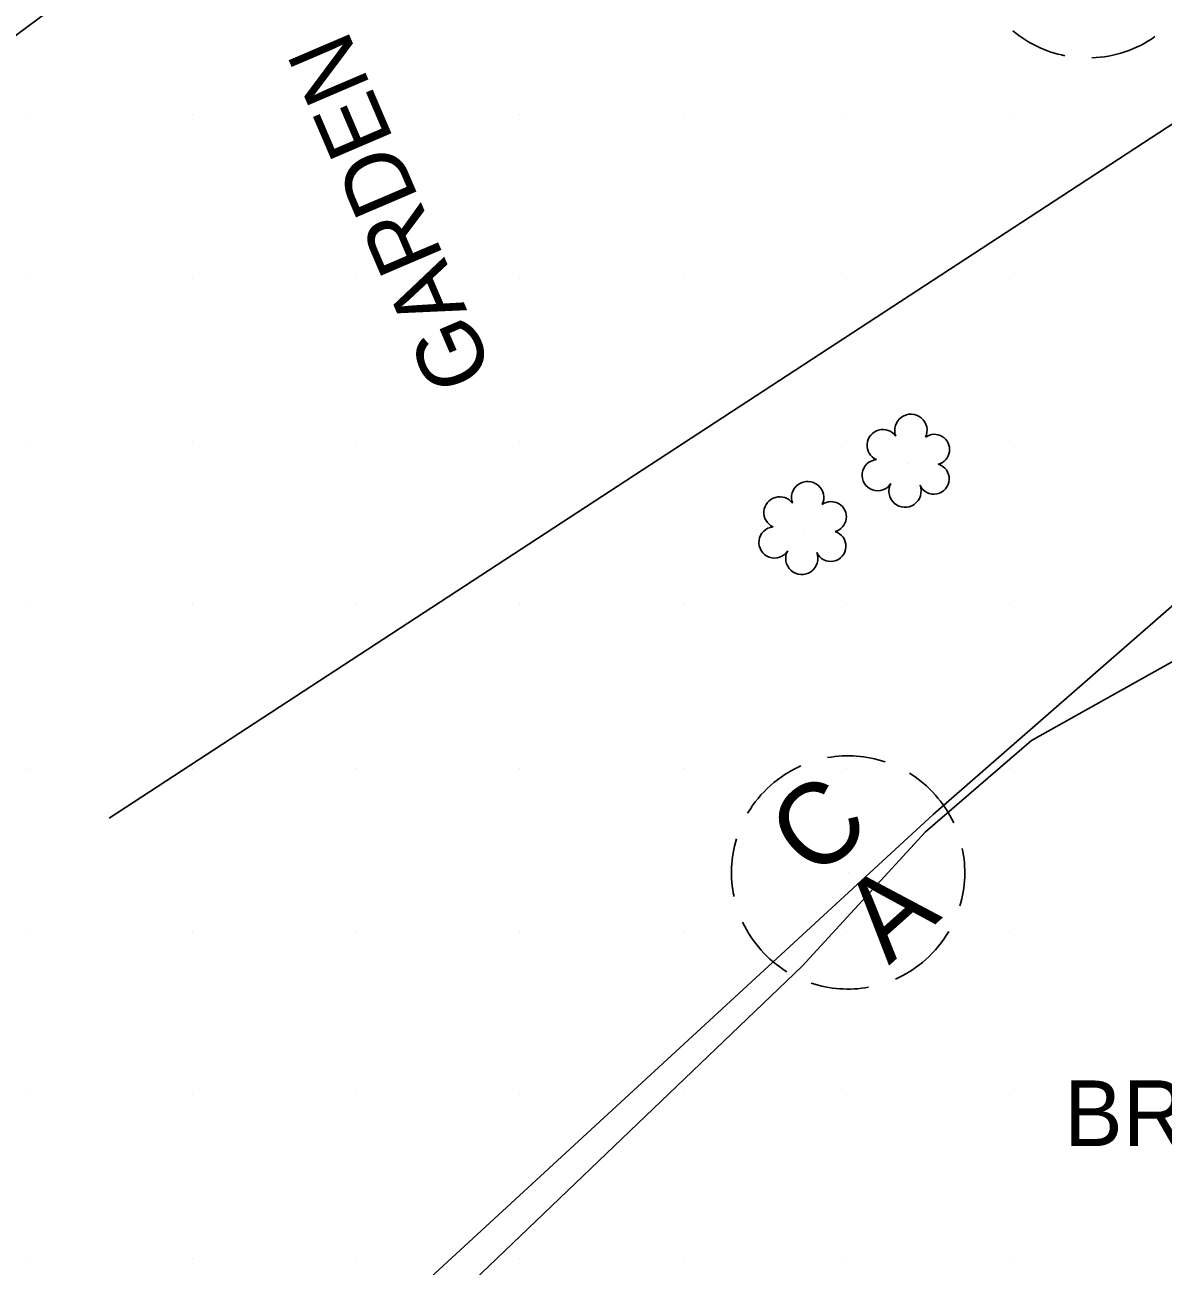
# Model space of a CAD drawing. Extents: x 1548934 to 1561348, y 809680 to 824075.
# Drawn here: x 1551639.7 to 1551709.4, y 810839.5 to 810915.5 of the extents above; entities that cross this region are included whole.
import ezdxf

# ---------------------------------------------------------------- set-up
doc = ezdxf.new("R2010")
doc.units = 0
for name, color, linetype in [('E_NCDOT_Vertical_Profile_Ground_Line', 7, 'Continuous'), ('Exist DTM QL2 LIDAR Elevation Point', 7, 'Continuous'), ('Exist Other Culture Area Outline', 7, 'Continuous'), ('Exist Other Culture Area Outline Text', 7, 'Continuous'), ('Exist Right of Way Control of Access CA Symbol CELL', 7, 'Continuous'), ('Exist Structure Major Bridge Seat Top Elevation', 7, 'Continuous'), ('Exist Vegetation Shrub CELL', 7, 'Continuous'), ('Exist Vegetation Woods Line', 7, 'Continuous'), ('P_NCDOT_Vertical_Profile_Grade_Minor_Road', 7, 'Continuous'), ('P_RDY_Dimension_Text', 7, 'Continuous')]:
    doc.layers.add(name, color=color, linetype=linetype)

msp = doc.modelspace()

# ---------------------------------------------------------------- linework, layer by layer
at = {"layer": 'E_NCDOT_Vertical_Profile_Ground_Line'}
for points in [[(1551669.226, 811276.996), (1551672.738, 811263.647), (1551679.608, 811234.972), (1551690.372, 811191.216), (1551702.412, 811145.663), (1551714.334, 811100.035), (1551727.001, 811053.454), (1551740.473, 811006.496), (1551755.133, 810959.341), (1551769.097, 810915.847), (1551778.934, 810888.327), (1551783.173, 810876.085)], [(1551650.087, 811272.175), (1551653.545, 811258.382), (1551661.249, 811229.547), (1551671.78, 811185.408), (1551683.851, 811140.035), (1551696.074, 811094.565), (1551708.619, 811047.914), (1551722.358, 811000.566), (1551736.976, 810952.927), (1551751.546, 810908.962), (1551760.885, 810880.923), (1551765.285, 810868.443)]]:
    msp.add_open_spline(points, degree=3, dxfattribs=at)
at = {"layer": 'Exist DTM QL2 LIDAR Elevation Point'}
for p, q in [((1551639.99, 810910.004), (1551639.99, 810910.004)), ((1551649.991, 810910.004), (1551649.991, 810910.004)), ((1551659.992, 810910.004), (1551659.992, 810910.004)), ((1551669.992, 810910.004), (1551669.992, 810910.004)), ((1551679.993, 810910.004), (1551679.993, 810910.004)), ((1551689.994, 810910.004), (1551689.994, 810910.004)), ((1551699.995, 810910.004), (1551699.995, 810910.004)), ((1551639.99, 810900.003), (1551639.99, 810900.003)), ((1551649.991, 810900.003), (1551649.991, 810900.003)), ((1551659.992, 810900.003), (1551659.992, 810900.003)), ((1551669.992, 810900.003), (1551669.992, 810900.003)), ((1551679.993, 810900.003), (1551679.993, 810900.003)), ((1551689.994, 810900.003), (1551689.994, 810900.003)), ((1551699.995, 810900.003), (1551699.995, 810900.003)), ((1551639.99, 810890.002), (1551639.99, 810890.002)), ((1551649.991, 810890.002), (1551649.991, 810890.002)), ((1551659.992, 810890.002), (1551659.992, 810890.002)), ((1551669.992, 810890.002), (1551669.992, 810890.002)), ((1551679.993, 810890.002), (1551679.993, 810890.002)), ((1551689.994, 810890.002), (1551689.994, 810890.002)), ((1551699.995, 810890.002), (1551699.995, 810890.002)), ((1551639.99, 810880.001), (1551639.99, 810880.001)), ((1551649.991, 810880.001), (1551649.991, 810880.001)), ((1551659.992, 810880.001), (1551659.992, 810880.001)), ((1551669.992, 810880.001), (1551669.992, 810880.001)), ((1551679.993, 810880.001), (1551679.993, 810880.001)), ((1551689.994, 810880.001), (1551689.994, 810880.001)), ((1551699.995, 810880.001), (1551699.995, 810880.001)), ((1551639.99, 810870), (1551639.99, 810870)), ((1551649.991, 810870), (1551649.991, 810870)), ((1551659.992, 810870), (1551659.992, 810870)), ((1551669.992, 810870), (1551669.992, 810870)), ((1551679.993, 810870), (1551679.993, 810870)), ((1551689.994, 810870), (1551689.994, 810870)), ((1551699.995, 810870), (1551699.995, 810870)), ((1551639.99, 810860), (1551639.99, 810860)), ((1551649.991, 810860), (1551649.991, 810860)), ((1551659.992, 810860), (1551659.992, 810860)), ((1551669.992, 810860), (1551669.992, 810860)), ((1551679.993, 810860), (1551679.993, 810860)), ((1551689.994, 810860), (1551689.994, 810860)), ((1551699.995, 810860), (1551699.995, 810860)), ((1551639.99, 810849.999), (1551639.99, 810849.999)), ((1551649.991, 810849.999), (1551649.991, 810849.999)), ((1551659.992, 810849.999), (1551659.992, 810849.999)), ((1551669.992, 810849.999), (1551669.992, 810849.999)), ((1551679.993, 810849.999), (1551679.993, 810849.999)), ((1551689.994, 810849.999), (1551689.994, 810849.999)), ((1551699.995, 810849.999), (1551699.995, 810849.999)), ((1551639.99, 810839.998), (1551639.99, 810839.998)), ((1551649.991, 810839.998), (1551649.991, 810839.998)), ((1551659.992, 810839.998), (1551659.992, 810839.998)), ((1551669.992, 810839.998), (1551669.992, 810839.998)), ((1551679.993, 810839.998), (1551679.993, 810839.998)), ((1551689.994, 810839.998), (1551689.994, 810839.998)), ((1551699.995, 810839.998), (1551699.995, 810839.998))]:
    msp.add_line(p, q, dxfattribs=at)
at = {"layer": 'Exist Other Culture Area Outline'}
for p, q in [((1551630.998, 810908.815), (1551700.718, 810960.615)), ((1551716.925, 810913.996), (1551644.86, 810866.935))]:
    msp.add_line(p, q, dxfattribs=at)
at = {"layer": 'Exist Right of Way Control of Access CA Symbol CELL'}
msp.add_line((1551690.094, 810863.607), (1551690.094, 810863.607), dxfattribs=at)
for centre, start, end in [((1551704.752, 810920.617), 230.21678, 258.8046), ((1551704.752, 810920.617), 272.03783, 305.19661), ((1551690.094, 810863.607), 71.53495, 100.12277), ((1551690.094, 810863.607), 113.91621, 149.52844), ((1551690.094, 810863.607), 25.14294, 58.30172), ((1551690.094, 810863.607), 163.32189, 191.9097), ((1551690.094, 810863.607), 343.32189, 11.9097), ((1551690.094, 810863.607), 205.14294, 238.30172), ((1551690.094, 810863.607), 293.91621, 329.52844), ((1551690.094, 810863.607), 251.53495, 280.12277)]:
    msp.add_arc(centre, 7.14, start, end, dxfattribs=at)
at = {"layer": 'Exist Vegetation Shrub CELL'}
for p, q in [((1551693.705, 810888.635), (1551693.705, 810888.635)), ((1551687.385, 810884.515), (1551687.385, 810884.515))]:
    msp.add_line(p, q, dxfattribs=at)
for centre, radius, start, end in [((1551693.933, 810890.675), 0.99, 334.83907, 200.47174), ((1551692.222, 810889.762), 0.968, 35.89076, 245.42165), ((1551695.377, 810889.504), 0.929, 284.45672, 126.08612), ((1551691.904, 810887.931), 0.955, 95.10992, 327.95341), ((1551695.342, 810887.706), 0.937, 204.99133, 73.46012), ((1551687.614, 810886.555), 0.99, 334.83907, 200.47174), ((1551693.576, 810886.951), 0.984, 151.27966, 21.38702), ((1551685.902, 810885.642), 0.968, 35.89076, 245.42165), ((1551689.057, 810885.384), 0.929, 284.45672, 126.08612), ((1551685.585, 810883.811), 0.955, 95.10992, 327.95341), ((1551689.022, 810883.586), 0.937, 204.99133, 73.46012), ((1551687.257, 810882.831), 0.984, 151.27966, 21.38702)]:
    msp.add_arc(centre, radius, start, end, dxfattribs=at)
at = {"layer": 'Exist Vegetation Woods Line'}
msp.add_lwpolyline([(1551659.009, 810830.794), (1551687.273, 810857.868), (1551694.83, 810866.102), (1551701.312, 810871.679), (1551710.401, 810876.775), (1551717.053, 810878.29), (1551720.9, 810876.861), (1551733.666, 810867.652), (1551749.063, 810849.427), (1551750.485, 810843.047), (1551748.423, 810838.374)], dxfattribs=at)
at = {"layer": 'P_NCDOT_Vertical_Profile_Grade_Minor_Road'}
msp.add_open_spline([(1551774.266, 810871.875), (1551769.963, 810884.281), (1551760.748, 810912.225), (1551745.661, 810955.91), (1551731.498, 811003.541), (1551717.995, 811050.78), (1551705.433, 811097.256), (1551693.244, 811142.664), (1551681.433, 811187.985), (1551670.2, 811231.948), (1551663.062, 811260.975), (1551659.556, 811274.891)], degree=3, dxfattribs=at)
at = {"layer": 'P_RDY_Dimension_Text'}
msp.add_lwpolyline([(1551760.849, 810852.377), (1551753.881, 810847.549), (1551716.432, 810885.612), (1551695.287, 810867.156), (1551642.57, 810818.585), (1551625.512, 810802.672), (1551609.652, 810768.783), (1551603.272, 810753.552)], dxfattribs=at)

# ---------------------------------------------------------------- texts
at = {"layer": 'Exist Other Culture Area Outline Text'}
msp.add_text('GARDEN', height=4.02, rotation=113.17361, dxfattribs=at).set_placement((1551668.424, 810894.181))
at = {"layer": 'Exist Right of Way Control of Access CA Symbol CELL'}
for s, p in [('C', (1551688.077, 810863.056)), ('A', (1551692.585, 810857.895))]:
    msp.add_text(s, height=5, rotation=41.72233, dxfattribs=at).set_placement(p)
at = {"layer": 'Exist Structure Major Bridge Seat Top Elevation'}
msp.add_text("BRIDGE SEAT=735.89'", height=4.02, dxfattribs=at).set_placement((1551703.311, 810846.855))

doc.saveas('drawing.dxf')
